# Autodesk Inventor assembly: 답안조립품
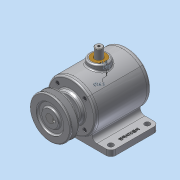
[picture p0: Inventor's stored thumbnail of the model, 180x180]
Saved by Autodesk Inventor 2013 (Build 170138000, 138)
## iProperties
Created: 2015-08
Part Number: 답안조립품
Document SubType Name: Assembly
Designer: Administrator
Author: Administrator
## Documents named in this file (14)
- C:\Users\Administrator\Desktop\350806V1017-1\답안조립품.iam
- C:\Users\Administrator\Desktop\350806V1017-1\본체.ipt
- C:\Users\Administrator\Desktop\350806V1017-1\앞커버.ipt
- C:\Users\Administrator\Desktop\350806V1017-1\베어링 6203.ipt
- C:\Users\Administrator\Desktop\350806V1017-1\오일실.ipt
- C:\Users\Administrator\Desktop\350806V1017-1\M4-소켓머리.ipt
- C:\Users\Administrator\Desktop\350806V1017-1\뒷커버.ipt
- C:\Users\Administrator\Desktop\350806V1017-1\부시.ipt
- C:\Users\Administrator\Desktop\350806V1017-1\축.ipt
- C:\Users\Administrator\Desktop\350806V1017-1\슬라이더.ipt
- C:\Users\Administrator\Desktop\350806V1017-1\스프링1 [가변부품].ipt
- C:\Users\Administrator\Desktop\350806V1017-1\KS B 1311 - 5 x 5 x 18I.ipt
- C:\Users\Administrator\Desktop\350806V1017-1\V-벨트풀리.ipt
- C:\Users\Administrator\Desktop\350806V1017-1\KS B 1028  - 납작점M4x5.ipt
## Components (14 placed, 6 different names)
1. 7-베어링 6203:1
2. 8-오일실:1
3. 7-베어링 6203:2
4. KS B 1311 (I) 5 x 5 x 18:1 — 각도:2, 각도:3
5. V-벨트풀리:1 — 각도:3
6. KS B 1028 납작점 - 미터 납작점M4x5:1
7. 9-M4-소켓머리:1
8. 9-M4-소켓머리:2
9. 9-M4-소켓머리:3
10. 9-M4-소켓머리:4
11. 9-M4-소켓머리:5
12. 9-M4-소켓머리:6
13. 9-M4-소켓머리:7
14. 9-M4-소켓머리:8
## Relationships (2: Angle 2)
- 각도:2 [Angle]: KS B 1311 (I) 5 x 5 x 18:1
- 각도:3 [Angle]: KS B 1311 (I) 5 x 5 x 18:1 ↔ V-벨트풀리:1
